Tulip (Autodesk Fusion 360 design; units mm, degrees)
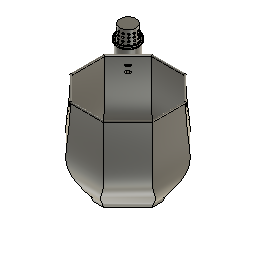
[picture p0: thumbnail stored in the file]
parameter "wall" = 1.35
parameter "height" = 127.5 (= "Size * 0.75") comment "Vase Hight (Medium setting)"
parameter "tolerance" = 0.15
sketch "Sketch1" plane through (0, 0, 0) normal (0, 0, 1) x axis (1, 0, 0)
  line L1 (-80.8652, -80.8652) -> (80.8652, -80.8652)
  line L2 (-80.8652, 80.8652) -> (-80.8652, -80.8652)
  line L3 (80.8652, 80.8652) -> (-80.8652, 80.8652)
  line L4 (80.8652, -80.8652) -> (80.8652, 80.8652)
  line L5 (-80.8652, 80.8652) -> (80.8652, -80.8652)
  line L6 (80.8652, 80.8652) -> (-80.8652, -80.8652)
  line L7 (-77.3297, 84.4007) -> (84.4007, -77.3297)
  line L8 (-84.4007, 77.3297) -> (77.3297, -84.4007)
  line L9 (-47.4097, 47.4097) -> (39.1401, 47.4097)
  line L10 (-47.4097, -39.1401) -> (-47.4097, 47.4097)
  line L11 (39.1401, -39.1401) -> (-47.4097, -39.1401)
  line L12 (39.1401, 47.4097) -> (39.1401, -39.1401)
  line L13 (-47.4097, -39.1401) -> (39.1401, 47.4097)
  line L14 (39.1401, -39.1401) -> (-47.4097, 47.4097)
  line L15 (-4.1348, 80.8652) -> (-4.1348, 4.1348)
  line L16 (-0.5993, 7.6703) -> (-7.6703, 0.5993)
  line L17 (-62.3297, 69.4007) -> (-69.4007, 62.3297)
  circle C1 centre (-4.1348, 4.1348) radius 85
  circle C2 centre (-65.8652, 65.8652) radius 15
  circle C3 centre (-4.1348, 4.1348) radius 61.2
  circle C4 centre (-65.8652, 65.8652) radius 13.65
  circle C5 centre (-65.8652, 65.8652) radius 13.5
  circle C6 centre (-4.1348, 4.1348) radius 72.3
  point P6 (0, 0)
  point P1 (0, 0)
  point P7 (-4.1348, 4.1348)
  point P8 (-65.8652, 65.8652)
  point P9 (-4.1348, 4.1348)
  point P19 (-4.1348, 4.1348)
  point P15 (39.1401, 47.4097)
  point P20 (-4.1348, 4.1348)
  point P21 (-4.1348, 80.8652)
  point P22 (-7.6703, 0.5993)
  point P23 (-0.5993, 7.6703)
  point P26 (-4.1348, 4.1348)
  point P27 (-69.4007, 62.3297)
  point P28 (-62.3297, 69.4007)
  point P24 (-65.8652, 65.8652)
  horizontal L1
  perpendicular L1 L2
  parallel L1 L3
  parallel L2 L4
  coincident L5 P6
  coincident L6 P6
  coincident P1 P6
  coincident L5 P7
  coincident L5 P8
  tangent L3 C2
  tangent L4 C1
  coincident P7 P9
  perpendicular L9 L10
  parallel L9 L11
  parallel L10 L12
  coincident L13 P19
  coincident L14 P19
  coincident P9 P19
  equal L9 L12
  coincident C3 P15
  coincident P9 P20
  coincident L3 P21
  perpendicular L3 L15
  coincident L8 P22
  coincident L7 P23
  perpendicular L7 L16
  equal L2 L3
  midpoint P19 L16
  coincident P19 P26
  tangent C2 C6
  coincident L8 P27
  coincident L7 P28
  perpendicular L7 L17
  coincident P24 L17
  dimension "Size" diameter C1 = 170
  dimension "d5" diameter C2 = 30
  dimension "d8" = 5
  dimension "d9" = -5
  dimension "d16" = -23.8 (= "-Size * 0.14")
  dimension "d17" angle L13 L15 = 45
  dimension "d81" distance P7 P8 = 87.3 (= "Size * 0.45 + ( wall * 8 )")
work_plane "WorkPlane1" AlongDistance 9.1071 (= "height / 14")
work_plane "WorkPlane2" AlongDistance 127.5 (= "height")
work_plane "WorkPlane5" AlongDistance 76.5 (= "height * 0.6")
work_plane "WorkPlane4" RotateAngle 90
sketch "Sketch2" plane through (0, 0, 9.1071) normal (0, 0, 1) x axis (1, 0, 0)
  line L1 (-4.1348, 89.1348) -> (-4.1348, 4.1348)
  line L2 (-51.016, 51.016) -> (42.7464, 51.016)
  line L3 (-51.016, -42.7464) -> (-51.016, 51.016)
  line L4 (42.7464, -42.7464) -> (-51.016, -42.7464)
  line L5 (42.7464, 51.016) -> (42.7464, -42.7464)
  line L6 (-51.016, -42.7464) -> (42.7464, 51.016)
  line L7 (42.7464, -42.7464) -> (-51.016, 51.016)
  circle C1 centre (-4.1348, 4.1348) radius 85
  circle C2 centre (-4.1348, 4.1348) radius 66.3
  point P2 (-4.1348, 4.1348)
  point P4 (-4.1348, 4.1348)
  point P5 (-4.1348, 89.1348)
  point P10 (-4.1348, 4.1348)
  point P6 (42.7464, 51.016)
  coincident P2 P4
  coincident C1 P5
  vertical L1
  perpendicular L2 L3
  parallel L2 L4
  parallel L3 L5
  coincident L6 P10
  coincident L7 P10
  coincident P2 P10
  equal L2 L5
  coincident C2 P6
  dimension "d14" = -18.7 (= "-Size * 0.11")
  dimension "d15" angle L1 L6 = 45
sketch "Sketch3" plane through (0, 0, 127.5) normal (0, 0, 1) x axis (1, 0, 0)
  line L1 (-64.2389, 64.2389) -> (55.9693, 64.2389)
  line L2 (-64.2389, -55.9693) -> (-64.2389, 64.2389)
  line L3 (55.9693, -55.9693) -> (-64.2389, -55.9693)
  line L4 (55.9693, 64.2389) -> (55.9693, -55.9693)
  line L5 (-64.2389, -55.9693) -> (55.9693, 64.2389)
  line L6 (55.9693, -55.9693) -> (-64.2389, 64.2389)
  line L7 (-4.1348, 89.1348) -> (-4.1348, 4.1348)
  circle C1 centre (-4.1348, 4.1348) radius 85
  circle C2 centre (-65.8652, 65.8652) radius 15
  circle C3 centre (-65.8652, 65.8652) radius 7.5
  point P7 (-4.1348, 4.1348)
  point P2 (-4.1348, 4.1348)
  point P3 (55.9693, 64.2389)
  point P8 (-4.1348, 4.1348)
  point P9 (-4.1348, 89.1348)
  perpendicular L1 L2
  parallel L1 L3
  parallel L2 L4
  coincident L5 P7
  coincident L6 P7
  coincident P2 P7
  equal L1 L4
  coincident C1 P3
  coincident P2 P8
  coincident C1 P9
  vertical L7
  concentric C2 C3
  dimension "d18" angle L5 L7 = 45
  dimension "d126" diameter C3 = 15
sketch "Sketch9" plane through (0, 0, 76.5) normal (0, 0, 1) x axis (1, 0, 0)
  circle C1 centre (-65.8652, 65.8652) radius 13.65
  circle C2 centre (-65.8652, 65.8652) radius 11
  concentric C1 C2
  dimension "d127" diameter C2 = 22
loft "Loft2" sketch "Sketch1" + "Sketch9" + "Sketch3" Start Weight 4.0298 Start TakeOff Angle 0 End Weight -3.9427 End TakeOff Angle 0
loft "Loft1" sketch "Sketch1" + "Sketch2" + "Sketch3" Start Weight 1.991 Start TakeOff Angle 0 End Weight -1.8239 End TakeOff Angle 0
chamfer "Chamfer4" distance 35.7 (= "Size * 0.21")
extrude "Extrude2" new body sketch "Sketch1" profile of C1 C2 L7 L8 C3 L9 L10 L16 C4 C5 C6 L17 blind 15 from offset 3
extrude "Extrude3" sketch "Sketch1" profile of C1 C2 L7 L8 C3 L9 L10 L16 C4 C5 C6 L17 blind -15 from offset -10
chamfer "Chamfer1" distance 1.35 (= "wall")
fillet "Fillet1" radius 3
extrude "Extrude17" sketch "Sketch1" profile of C1 L7 L8 C5 blind 20 taper -5
shell "Shell1" innerThickness 1.35 (= "wall")
extrude "Extrude18" add sketch "Sketch1" profile of C1 C2 L7 L8 C4 C5 along normal blind 20 taper -3
extrude "Extrude16" cut sketch "Sketch1" profile of C1 L7 L8 C4 C5 along normal blind 20 taper -5
offset_faces "OffsetFaces5" distance 1.35 (= "wall")
sketch "Sketch6" plane through (0, 0, 127.5) normal (0, 0, 1) x axis (-1, 0, 0)
  line L1 (65.8652, -49.3652) -> (65.8652, -82.3652)
  line L2 (58.1973, -51.2552) -> (73.5331, -80.4752)
  line L3 (52.286, -56.4921) -> (79.4444, -75.2383)
  line L4 (49.4855, -63.8764) -> (82.2449, -67.8541)
  line L5 (50.4374, -71.7162) -> (81.293, -60.0142)
  line L6 (54.9237, -78.2156) -> (76.8067, -53.5148)
  line L7 (61.9165, -81.8858) -> (69.8139, -49.8447)
  line L8 (69.8139, -81.8858) -> (61.9165, -49.8447)
  line L9 (76.8067, -78.2156) -> (54.9237, -53.5148)
  line L10 (81.293, -71.7162) -> (50.4374, -60.0142)
  line L11 (82.2449, -63.8764) -> (49.4855, -67.8541)
  line L12 (79.4444, -56.4921) -> (52.286, -75.2383)
  line L13 (73.5331, -51.2552) -> (58.1973, -80.4752)
  circle C1 centre (65.8652, -65.8652) radius 15.15
  circle C2 centre (65.8652, -65.8652) radius 16.5
  circle C3 centre (65.8652, -65.8652) radius 12.3
  circle C4 centre (65.8652, -65.8652) radius 15
  circle C5 centre (65.8652, -65.8652) radius 13.65
  point P5 (65.8652, -82.3652)
  point P6 (65.8652, -49.3652)
  point P3 (65.8652, -65.8652)
  coincident C2 P5
  coincident C2 P6
  vertical L1
  coincident P3 L1
  concentric C2 C4
  concentric C3 C5
  dimension "d115" distance C1 C2 = 1.35 (= "wall")
  dimension "d140" distance C1 C4 = 0.15 (= "tolerance")
  dimension "d141" distance C3 C5 = 1.35 (= "wall")
  dimension "d74" C-Pattern1-Angle = 360
extrude "Extrude7" add sketch "Sketch6" profile of C1 C2 C3 L1 L2 L3 L4 L5 L6 L7 L8 L9 L10 L11 L12 L13 no distance stored
extrude "Extrude6" add sketch "Sketch6" profile of C1 C2 L1 L2 L3 L4 L5 L6 L7 L8 L9 L10 L11 L12 L13 along normal blind 2 taper -5
extrude "Extrude8" cut sketch "Sketch6" profile of C3 L1 L2 L3 L4 L5 L6 L7 L8 L9 L10 L11 L12 L13 C5 along normal blind 2.5
rectangular_pattern "R-Pattern1" uSpaceDistance 4.5 vSpaceDistance 0
chamfer "Chamfer5" distance 0.8
circular_pattern "C-Pattern1" countU 13 TotalAngle 360
chamfer "Chamfer7" distance 2.7 (= "wall * 2") distance 1.5 (= "wall + tolerance")
sketch "Sketch7" plane through (-4.1348, 4.1348, 0) normal (0.7071, -0.7071, 0) x axis (0.7071, 0.7071, 0)
  line L1 (3.65, 6) -> (3.65, 15)
  line L2 (-3.65, 15) -> (-3.65, 6)
  line L3 (5, 15) -> (5, 6)
  line L4 (-5, 6) -> (-5, 15)
  line L5 (-3.65, 114.5) -> (-3.65, 105.5)
  line L6 (3.65, 105.5) -> (3.65, 114.5)
  line L7 (5, 114.5) -> (5, 105.5)
  line L8 (-5, 105.5) -> (-5, 114.5)
  line L9 (-2, 4.35) -> (2, 4.35)
  line L10 (2, 16.65) -> (-2, 16.65)
  line L11 (2, 3) -> (-2, 3)
  line L12 (-2, 18) -> (2, 18)
  line L13 (-2, 103.85) -> (2, 103.85)
  line L14 (2, 116.15) -> (-2, 116.15)
  line L15 (-2, 117.5) -> (2, 117.5)
  line L16 (2, 102.5) -> (-2, 102.5)
  line L17 (2, 105.5) -> (-2, 114.5)
  line L18 (2, 6) -> (-2, 15)
  line L19 (2, 112.85) -> (-2, 112.85)
  line L20 (2, 107.15) -> (-2, 107.15)
  line L21 (2, 13.35) -> (-2, 13.35)
  line L22 (2, 7.65) -> (-2, 7.65)
  arc A1 centre (-2, 6) radius 1.65 clockwise from (-2, 4.35) to (-3.65, 6)
  arc A2 centre (-2, 15) radius 1.65 clockwise from (-3.65, 15) to (-2, 16.65)
  arc A3 centre (-2, 6) radius 3 clockwise from (-2, 3) to (-5, 6)
  arc A4 centre (-2, 15) radius 3 clockwise from (-5, 15) to (-2, 18)
  arc A5 centre (2, 105.5) radius 1.65 clockwise from (3.65, 105.5) to (2, 103.85)
  arc A6 centre (2, 114.5) radius 1.65 clockwise from (2, 116.15) to (3.65, 114.5)
  arc A7 centre (2, 105.5) radius 3 clockwise from (5, 105.5) to (2, 102.5)
  arc A8 centre (2, 114.5) radius 3 clockwise from (2, 117.5) to (5, 114.5)
  arc A9 centre (2, 6) radius 1.65 clockwise from (3.65, 6) to (2, 4.35)
  arc A10 centre (2, 15) radius 1.65 clockwise from (2, 16.65) to (3.65, 15)
  arc A11 centre (2, 6) radius 3 clockwise from (5, 6) to (2, 3)
  arc A12 centre (2, 15) radius 3 clockwise from (2, 18) to (5, 15)
  arc A13 centre (-2, 105.5) radius 1.65 clockwise from (-2, 103.85) to (-3.65, 105.5)
  arc A14 centre (-2, 114.5) radius 1.65 clockwise from (-3.65, 114.5) to (-2, 116.15)
  arc A15 centre (-2, 114.5) radius 3 clockwise from (-5, 114.5) to (-2, 117.5)
  arc A16 centre (-2, 105.5) radius 3 clockwise from (-2, 102.5) to (-5, 105.5)
  circle C1 centre (2, 114.5) radius 1.65
  circle C2 centre (-2, 114.5) radius 1.65
  circle C3 centre (-2, 105.5) radius 1.65
  circle C4 centre (2, 105.5) radius 1.65
  circle C5 centre (0, 110) radius 1.65
  circle C6 centre (2, 15) radius 1.65
  circle C7 centre (-2, 15) radius 1.65
  circle C8 centre (-2, 6) radius 1.65
  circle C9 centre (2, 6) radius 1.65
  circle C10 centre (0, 10.5) radius 1.65
  point P39 (-2, 114.5)
  point P42 (-2, 114.5)
  point P20 (2, 105.5)
  point P43 (2, 105.5)
  point P19 (-2, 15)
  point P44 (-2, 15)
  point P27 (2, 6)
  point P45 (2, 6)
  point P49 (2, 105.5)
  point P50 (0, 110)
  point P52 (-2, 15)
  point P54 (2, 6)
  point P55 (0, 10.5)
  point P56 (-2, 112.85)
  point P57 (2, 112.85)
  point P58 (-2, 107.15)
  point P59 (2, 107.15)
  point P60 (-2, 13.35)
  point P61 (2, 13.35)
  point P62 (-2, 7.65)
  point P63 (2, 7.65)
  point P11 (2, 116.15)
  point P18 (-2, 6)
  point P53 (-2, 6)
  coincident P39 P42
  coincident P20 P43
  coincident P19 P44
  coincident P27 P45
  concentric A6 C1
  concentric A14 C2
  concentric A13 C3
  coincident P43 P49
  midpoint L17 P50
  concentric A10 C6
  coincident P44 P52
  coincident P45 P54
  midpoint L18 P55
  equal C1 C2
  equal C1 C5
  equal C1 C4
  equal C1 C3
  equal C1 C6
  equal C1 C7
  equal C1 C10
  equal C1 C9
  equal C1 C8
  coincident C2 P56
  coincident C1 P57
  tangent C1 L19
  horizontal L19
  coincident C3 P58
  coincident C4 P59
  tangent C4 L20
  parallel L19 L20
  coincident C7 P60
  coincident C6 P61
  tangent C6 L21
  parallel L20 L21
  coincident C8 P62
  coincident C9 P63
  tangent C9 L22
  parallel L21 L22
  coincident P11 C1
  coincident P18 P53
extrude "Extrude19" cut sketch "Sketch7" profile of L1 L2 L5 L6 A1 A2 A5 A6 A9 L9 L10 A10 L13 A13 A14 L14 C1 C2 C3 C4 C5 C6 C7 C8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 against normal blind 87.3 (magnitude of "-d81")
extrude "Extrude14" cut sketch "Sketch7" profile of A1 A2 A5 A6 A9 L9 L10 A10 L13 A13 A14 L14 C1 C2 C3 C4 C6 C7 C8 C9 L19 L20 L21 L22 against normal blind 85 (magnitude of "-Size / 2")
combine "Combine6"
remove_body "RemoveBody15"
remove_body "RemoveBody16"
combine "Combine7"
remove_body "RemoveBody19"
remove_body "RemoveBody20"
sketch "Sketch8" plane through (0, 0, 0) normal (0.7071, 0.7071, 0) x axis (-0.7071, 0.7071, 0)
  line L1 (106.1598, 107.0033) -> (80.6292, 102.5015)
  line L2 (66.3643, 103.85) -> (88.2767, 103.85)
  line L3 (106.1598, 107.0033) -> (106.1598, 108.3741)
  line L4 (106.1598, 108.3741) -> (80.5024, 103.85)
  curve K1 (106.5815, 20) -> (106.772, 123.4501)
  curve K2 (80.5024, 103.85) -> (79.7135, 20)
  curve K3 (79.5229, 123.4501) -> (79.7092, 116.15)
  point P6 (106.1598, 108.3741)
  point P5 (80.5024, 103.85)
  point P10 (80.5024, 103.85)
  point P15 (80.6292, 102.5015)
  point P2 (88.2767, 103.85)
  point P4 (66.3643, 103.85)
  point P14 (66.3643, 103.85)
  horizontal L2
  parallel L1 L4
  vertical L3
  coincident P6 K1
  coincident P5 P10
  coincident K2 P15
  coincident P2 L1
  coincident P4 P14
  dimension "d84" angle L1 L2 = 10
  dimension "d136" distance L1 L4 = 1.35 (= "wall")
extrude "Extrude11" new body sketch "Sketch8" profile of L1 L3 L4 distance 20
combine "Combine5"
remove_body "RemoveBody9"
remove_body "RemoveBody14"
work_plane "WorkPlane3" RotateAngle 90
sketch "Sketch5" plane through (-4.1348, 30, 100) normal (1, 0, 0) x axis (0, 1, 0)
  line L1 (32.8889, 27.5) -> (34.2389, 27.5)
  line L2 (33.5639, 26.5) -> (33.5639, 27.5)
  circle C1 centre (33.5639, 26.5) radius 1.25
  point P3 (34.2389, 27.5)
  point P4 (34.2389, 27.5)
  point P2 (32.8889, 27.5)
  point P5 (32.8889, 27.5)
  point P7 (33.5639, 27.5)
  point P6 (33.5639, 26.5)
  point P8 (33.5639, 26.5)
  coincident P3 P4
  coincident P2 P5
  midpoint L1 P7
  perpendicular L1 L2
  coincident P6 P8
  dimension "d36" diameter C1 = 2.5
  dimension "d135" distance P7 P8 = 1
sweep "Sweep1" sketch "Sketch5" TwistAngle 0 TaperAngle 0
combine "Combine8"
